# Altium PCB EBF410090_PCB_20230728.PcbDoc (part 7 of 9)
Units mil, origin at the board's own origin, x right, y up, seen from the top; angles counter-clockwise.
Board outline 5393.69 x 3858.26 mil, 6 copper layers (TOP, GND02, ART03, ART04, PWR05, BOTTOM), stack 47.2 mil thick; 570 components, 437 nets, 2015 pads, 1260 vias.
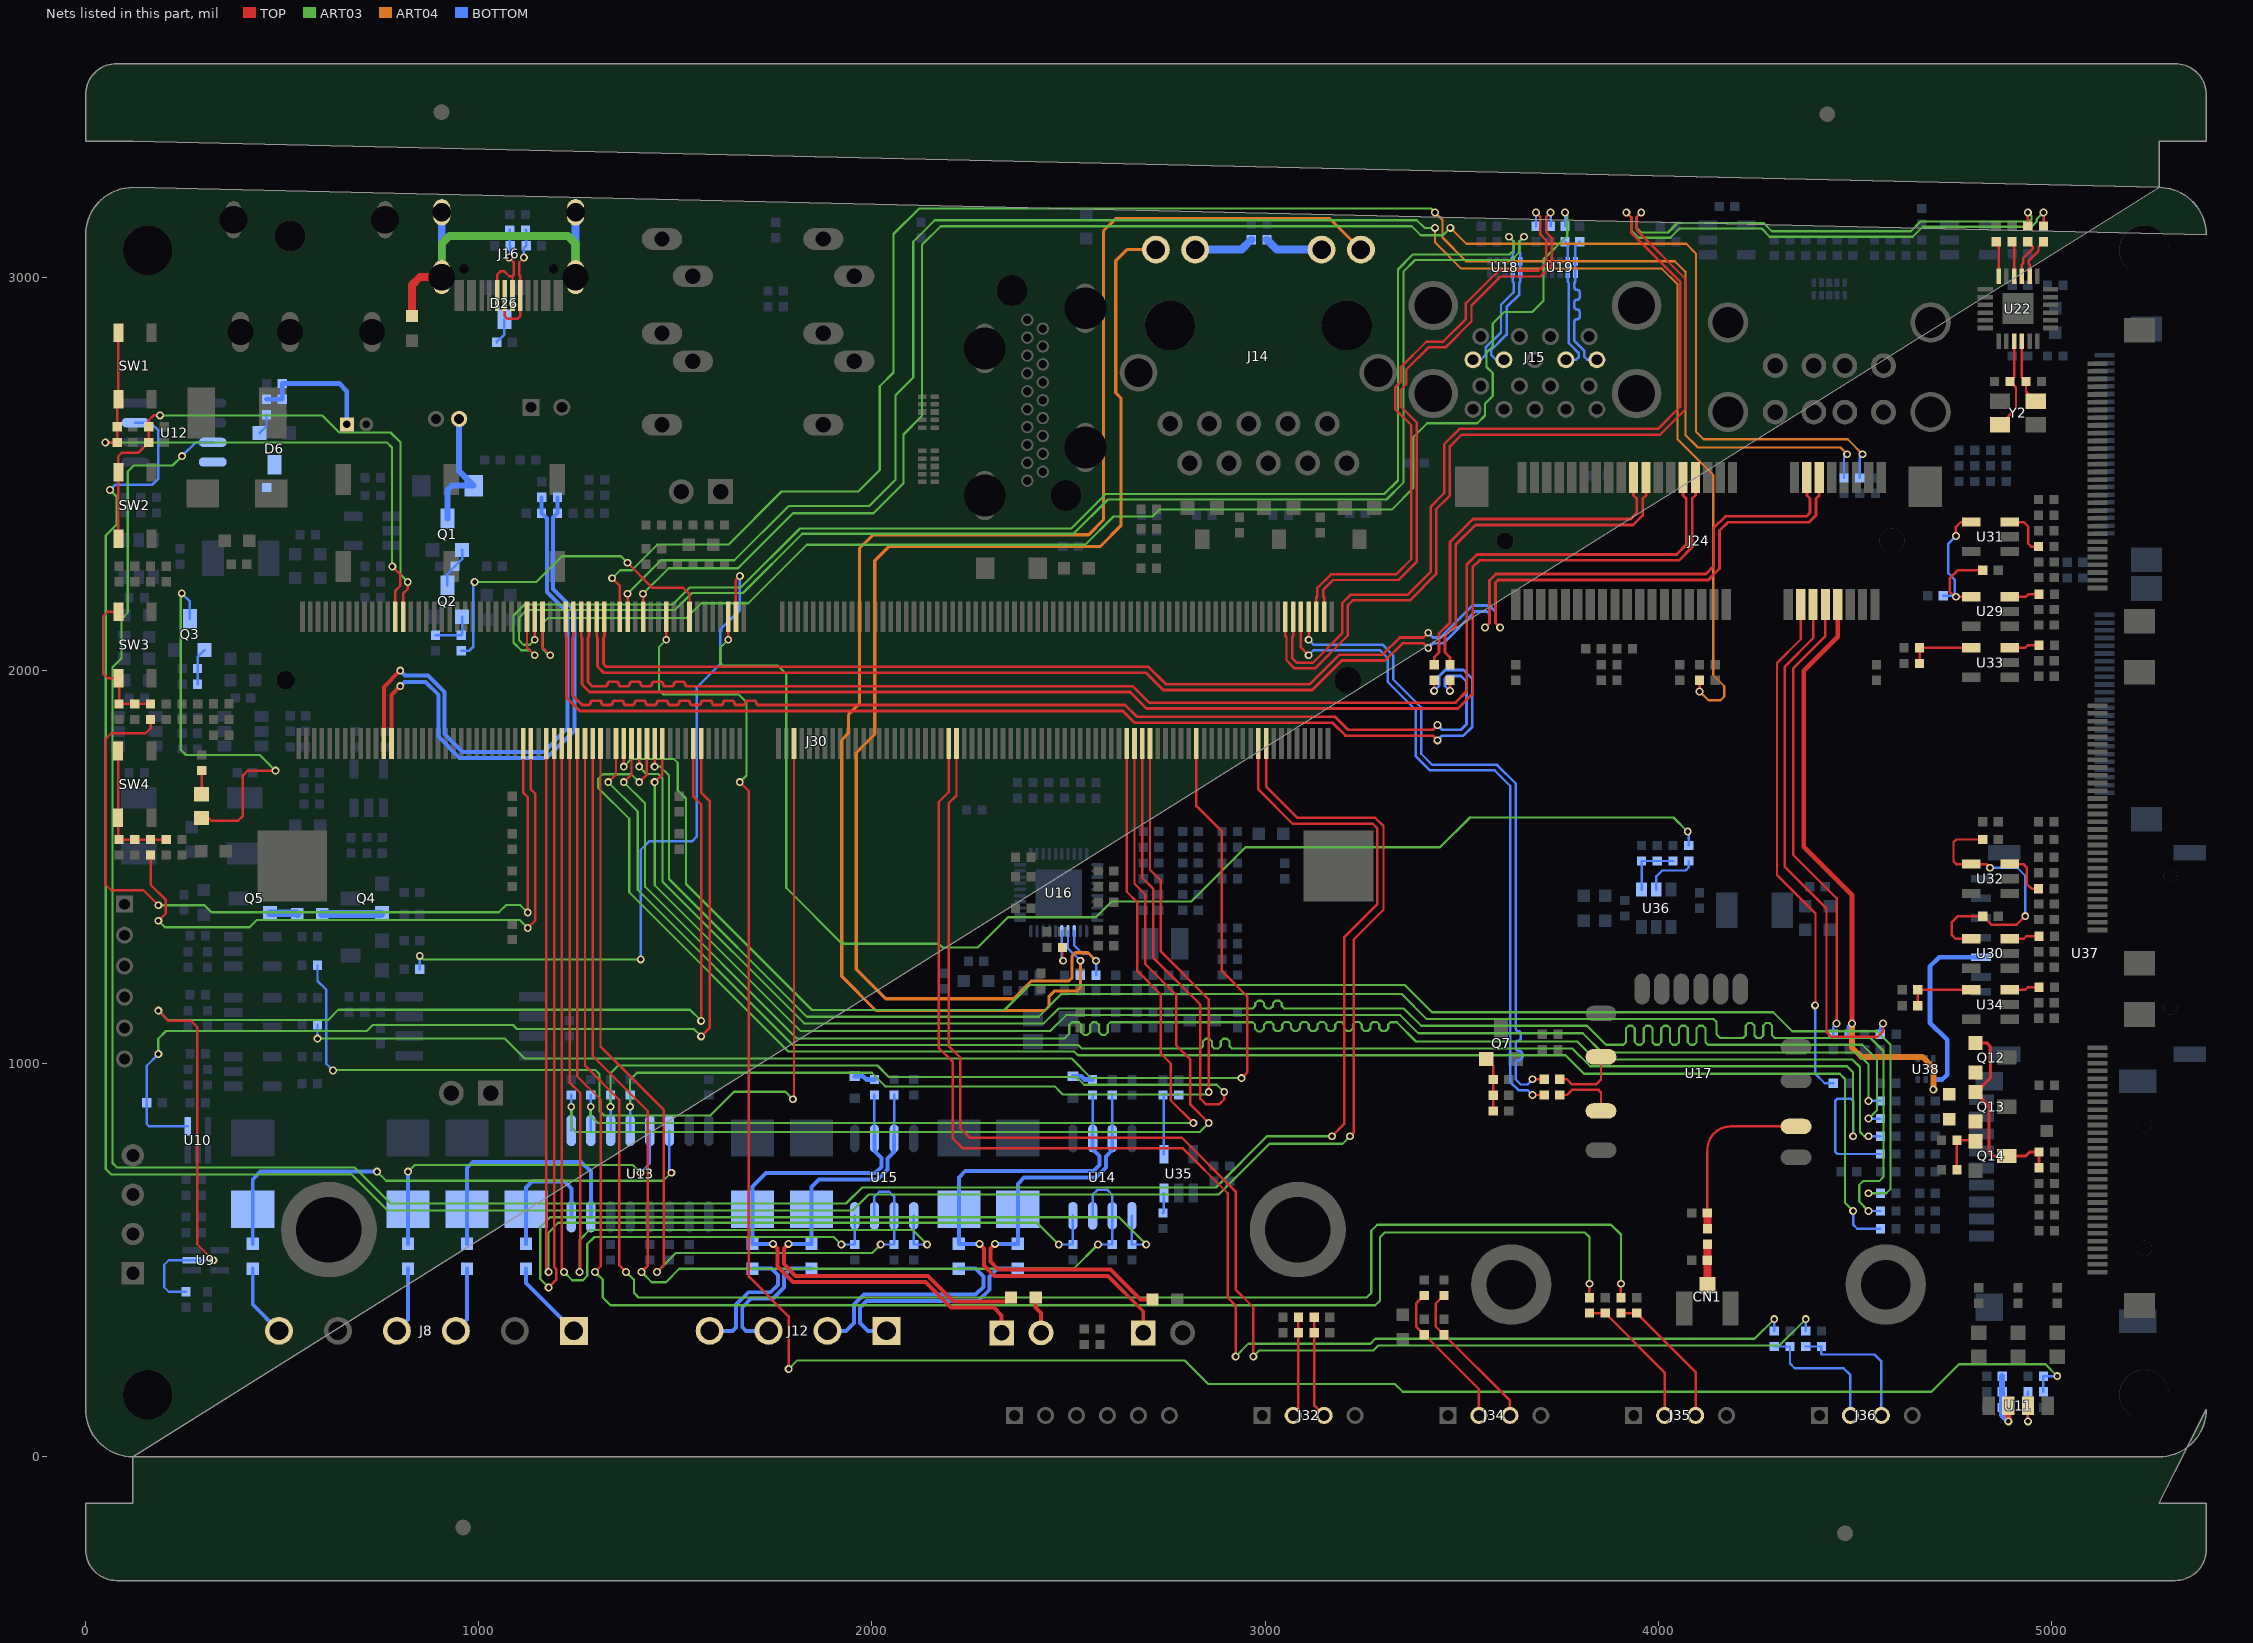
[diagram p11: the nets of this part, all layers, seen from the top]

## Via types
v1: diameter 20, hole 12, TOP to BOTTOM, 1260 vias

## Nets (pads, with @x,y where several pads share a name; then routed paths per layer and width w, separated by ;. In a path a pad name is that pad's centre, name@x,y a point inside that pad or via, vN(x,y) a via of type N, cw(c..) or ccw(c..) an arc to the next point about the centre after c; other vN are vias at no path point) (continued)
N17592172: C169.2 R203.2 R205.1 U36.4 | length 153.1
  BOTTOM w6.16: U36.4@3957.6,1442.24 R205.1@3957.6,1515.32 R203.2@3997.6,1515.32 C169.2@4037.6,1515.32
N17592286: R206.2 U36.5 | length 142.1
  BOTTOM w6.16: U36.5@3995,1442.24 3995,1476 4010,1491 4069.44,1491 4077.6,1499.16 R206.2@4077.6,1515.32
N17633217: C119.1 U22.3 Y2.1 | length 239.2
  TOP w6.16: Y2.1@4869.72,2625.47 4910,2665.75 4910,2719.68 C119.1@4894.68,2735 4905.16,2745.48 U22.3@4905.16,2837.32
N17633237: C120.2 U22.4 Y2.3 | length 167.5
  TOP w6.16: U22.4@4924.84,2837.32 4924.84,2745.48 C120.2@4935.32,2735 4935.32,2709.49 Y2.3@4960.28,2684.53
N17633305: R145.2 U22.16 | length 89.8
  TOP w6.16: R145.2@4900,3090.32 4905.16,3085.16 U22.16@4905.16,3002.68
N17633317: R146.2 U22.18 | length 90
  TOP w6.16: R146.2@4860,3090.32 4865.79,3084.53 U22.18@4865.79,3002.68
N17685591: C165.2 Q12.1 Q13.1 Q14.3 R196.2 | length 517.4
  TOP w8: Q12.1@4806.5,1052.5 4835.5,1052.5 4845,1043 4845,964 4808.5,927.5 Q13.1@4806.5,927.5 4841,893 4841,775 4851,765 Q14.3@4886.5,765 4935,765 4945,775 C165.2@4968.32,775 R196.2@4968.32,735
N17685601: Q14.1 R198.2 R199.1 | length 122.9
  TOP w6.16: R198.2@4759.68,730 R199.1@4759.68,805 4804,805 Q14.1@4806.5,802.5
N17685851: Q13.2 R194.2
N17690217: R195.1 U35.3 | length 52.2
  BOTTOM w6.16: R195.1@2740,619.68 2742.6,622.28 U35.3@2742.6,670.79
N17690290: C162.1 R193.2 U35.4 | length 192.2
  BOTTOM w6.16: U35.4@2742.6,769.21 2742.6,917.72 C162.1@2740,920.32 R193.2@2780,920.32
N17695706: C139.1 R172.2 U29.4 U31.4 | length 453.6
  TOP w6.16: v1(4757.19,2341.97) 4757.19,2365.08 4769.51,2377.4 U31.4@4795.79,2377.4 ; U29.4@4795.79,2187.4 v1(4757.19,2187.4) 4754.32,2187.4 4741,2200.72 4741,2233.68 4762.32,2255 C139.1@4825.32,2255
  BOTTOM w6.16: R172.2@4724.68,2190 v1@4754.59,2190 ; v1(4757.19,2187.4) v1@4754.59,2190 ; v1(4757.19,2341.97) 4738,2322.78 4738,2246.99 4754.59,2230.4 v1@4754.59,2190
N17695791: R175.1 U31.3 | length 124.6
  TOP w6.16: U31.3@4894.21,2377.4 4929.6,2377.4 4941,2366 4941,2322.16 4948.16,2315 R175.1@4967.32,2315
N17695827: R174.1 U29.3 | length 76.8
  TOP w6.16: U29.3@4894.21,2187.4 4935.4,2187.4 4942,2194 R174.1@4968.32,2194
N17697466: J14.13 R114.1 | length 153.2
  BOTTOM w20: J14.13@2822.1,3070.44 2940.12,3070.44 R114.1@2965,3095.32
N17697880: R182.1 U33.3 | length 76.8
  TOP w6.16: U33.3@4894.21,2057.4 4933.4,2057.4 4940,2064 R182.1@4968.32,2064
N17697953: C150.1 R180.2 U33.4 | length 171.1
  TOP w6.16: R180.2@4664.68,2017.4 C150.1@4664.68,2057.4 U33.4@4795.79,2057.4
N17701231: J11.2 R74.2 | length 95.6
  TOP w10: R74.2@2416.5,405 2416.5,379.25 2430,365.75 J11.2@2430,315
N17702194: J12.3 R81.2 | length 356
  BOTTOM w10: J12.3@1736.93,320.17 1679.83,320.17 1670,330 1670,380 1692.37,402.37 1748.63,402.37 1776.75,430.49 1776.75,461.24 1794.01,478.5 R81.2@1846.22,478.5
N17702199: J12.4 R82.2 | length 352.6
  BOTTOM w10: J12.4@1586.93,320.17 1645.17,320.17 1654,329 1654,386.63 1685.74,418.37 1742,418.37 1760.75,437.12 1760.75,462.5 1744.75,478.5 R82.2@1696.22,478.5
N17702222: J12.2 R80.2 | length 567.2
  BOTTOM w10: J12.2@1886.93,320.17 1934.17,320.17 1954,340 1954,386.63 1979.56,412.19 2263.5,412.19 2283.5,432.19 2283.5,458.5 2263.5,478.5 R80.2@2221.22,478.5
N17702231: J12.1 R79.2 | length 576.5
  BOTTOM w10: J12.1@2036.93,320.17 1989.83,320.17 1970,340 1970,380 1986.19,396.19 2270.13,396.19 2299.5,425.56 2299.5,458.5 2319.5,478.5 R79.2@2371.22,478.5
N17728858: D19.1 R71.1 | length 53.4
  BOTTOM w12: D19.1@2511.22,967.95 2532.06,967.95 2540.33,959.68 R71.1@2561.22,959.68
N17729021: D20.1 R72.1 | length 53.4
  BOTTOM w12: D20.1@1956.22,967.95 1977.06,967.95 1985.33,959.68 R72.1@2006.22,959.68
N17731599: J8.6 R59.2 | length 185.9
  BOTTOM w10: R59.2@425,478.5 425,386.83 J8.6@491.66,320.17
N17731608: J8.4 R58.2 | length 170.1
  BOTTOM w10: J8.4@791.66,320.17 820,348.51 R58.2@820,478.5
N17731627: J8.1 R56.2 | length 208.7
  BOTTOM w10: R56.2@1120,478.5 1120,441.83 J8.1@1241.66,320.17
N17748815: Q5.2 R26.2 | length 71
  BOTTOM w20: Q5.2@468.5,1382.5 536,1382.5 R26.2@538.5,1380
N17750545: Q1.1 Q2.3 R12.2 | length 105.5
  BOTTOM w6.16: Q2.3@920,2216.5 920,2245.32 R12.2@939.68,2265 957.5,2282.82 Q1.1@957.5,2306.5
N17750554: D2.1 J2.1 Q1.3 | length 328.6
  BOTTOM w15: Q1.3@920,2386.5 920,2457.99 932.01,2470 D2.1@986.93,2470 950.05,2506.88 J2.1@950.05,2639.93
N17750632: Q2.1 R17.2 R18.1 | length 112.9
  BOTTOM w6.16: R18.1@890,2089.68 R17.2@955,2089.68 957.5,2092.18 Q2.1@957.5,2136.5
N17759502: C67.1 D6.3 U12.8
N17770939: R142.1 U22.15 | length 104.6
  TOP w6.23: U22.15@4924.84,3002.68 4924.84,3032.16 4928.53,3035.85 4928.53,3048.65 4952.88,3073 4952.88,3077.44 R142.1@4940,3090.32
N17770942: R143.1 U22.14 | length 103.8
  TOP w6.23: U22.14@4944.53,3002.68 4944.53,3032.16 4942.76,3033.93 4942.76,3042.75 4967.11,3067.1 4967.11,3077.43 R143.1@4980,3090.32
N17861933: C65.1 C66.1 R47.1 U11.2 | length 160.8
  TOP w15: v1(4890.52,90) U11.2@4890.52,129.26
  BOTTOM w15: R47.1@4874.68,205 C66.1@4874.68,165 C65.1@4874.68,125 4874.68,105.84 v1(4890.52,90)
N17863087: R44.2 R46.2 U11.3 | length 114.3
  TOP w6.16: v1(4940.52,90) U11.3@4940.52,129.26
  BOTTOM w6.16: R46.2@4940.32,165 R44.2@4940.32,125 4940.32,90.2 v1(4940.52,90)
N17946485: C63.1 R43.1 SW3.3 SW3.4 Z5.2 | length 379.3
  TOP w6.16: SW3.4@82.99,2149.36 56.13,2149.36 44,2137.23 44,1992.19 56.13,1980.06 SW3.3@82.99,1980.06 85,1978.05 Z5.2@85,1914.68 C63.1@125,1914.68 R43.1@165,1914.68
N17975561: D7.2 J7.1 R50.2 R51.1 | length 337.8
  BOTTOM w12: R50.2@460,2689.68 R51.1@500,2689.68 499.68,2690 D7.2@499.68,2730 644.99,2730 664.37,2710.62 J7.1@664.37,2625.98
N18056005: C109.2 Q7.1 R127.2 R128.2 | length 139.4
  TOP w6.16: Q7.1@3562.5,1011.5 3580.32,993.68 C109.2@3580.32,959.44 R127.2@3580.32,919.44 R128.2@3580.32,879.44
N18056634: C106.1 C107.1 U17.2 | length 460.7
  TOP w6.16: C107.1@4125,619.68 C107.1@4124.68,620 4124.68,780.33 cw(c4184.42,780.33) 4184.42,840.07 U17.2@4350.45,840.07
  TOP w20: C106.1@4125,579.68 C107.1@4125,619.68
N18056637: C106.2 C108.1 CN1.1 | length 104.7
  TOP w6.16: C108.1@4125,499.68 C108.1@4124.68,500 C108.1@4125,500.32
  TOP w20: CN1.1@4125,435.86 C108.1@4125,499.68 ; C108.1@4125,500.32 C106.2@4125,540.32
N18057325: R126.2 U17.7 | length 172.9
  TOP w6.23: R126.2@3749.68,960 3767.78,960 3780.67,947.11 3841.92,947.11 3854.39,959.58 U17.7@3854.39,1017.23
N18057335: R125.2 U17.6 | length 159.8
  TOP w6.23: R125.2@3749.68,920 3767.79,920 3780.67,932.88 3848.16,932.88 3854.39,926.65 U17.6@3854.39,879.44
N18091011: D6.1 R50.1 | length 54.1
  BOTTOM w6.16: D6.1@442.5,2603.5 460,2621 R50.1@460,2650.32
N18111918: C136.1 R171.2 U30.4 U32.4 | length 722.7
  TOP w6.16: U30.4@4795.79,1317.4 4756.16,1317.4 4747,1326.56 4747,1360 4762,1375 C136.1@4825.32,1375 4847.32,1353 4911.37,1353 v1(4933.37,1375) ; R171.2@4825.32,1570 4758.16,1570 4751,1562.84 4751,1514.56 4758.16,1507.4 U32.4@4795.79,1507.4 4834.6,1507.4 v1(4844,1498)
  BOTTOM w6.16: v1(4844,1498) 4913,1498 4933.37,1477.63 v1(4933.37,1375)
N18111989: R176.1 U32.3 | length 123.4
  TOP w6.16: U32.3@4894.21,1507.4 4928.6,1507.4 4937,1499 4937,1457.32 4949.32,1445 R176.1@4967.32,1445
N18112037: R173.1 U30.3 | length 76.8
  TOP w6.16: U30.3@4894.21,1317.4 4929.4,1317.4 4936,1324 R173.1@4968.32,1324
N18115454: R188.1 U34.3 | length 76.8
  TOP w6.16: U34.3@4894.21,1187.4 4933.4,1187.4 4940,1194 R188.1@4968.32,1194
N18115527: C153.1 R187.2 U34.4 | length 176.1
  TOP w6.16: R187.2@4659.68,1147.4 C153.1@4659.68,1187.4 U34.4@4795.79,1187.4
N18173560: J16.C1 J16.C2 J16.C3 J16.C4 L8.1 | length 1020
  TOP w20: L8.1@830,2901.5 830,2980.28 850,3000.28 J16.C4@905.83,3000.28
  ART03 w20: J16.C4@905.83,3000.28 905.83,3085.75 925.08,3105 1226.78,3105 1246.03,3085.75 J16.C3@1246.03,3000.28
  BOTTOM w20: J16.C4@905.83,3000.28 J16.C2@905.83,3165.28 ; J16.C3@1246.03,3000.28 J16.C1@1246.03,3165.28
N18175084: D26.3 R138.1 | length 66.7
  BOTTOM w6.16: R138.1@1045.32,2835 1065,2854.68 D26.3@1065,2893.5
N18245213: LED4.1 Q3.3 | length 1038.3
  TOP w6.16: LED4.1@295,1624.68 312.37,1624.68 319.36,1617.69 387.68,1617.69 400,1630.01 400,1732.84 412.16,1745 v1(482.75,1745)
  ART03 w5.61: v1(244.37,2196) 242,2193.63 242,1798 255,1785 442.75,1785 v1(482.75,1745)
  BOTTOM w6.16: v1(244.37,2196) 265,2175.37 Q3.3@265,2131.5
N18245628: LED4.2 R16.2 | length 60
  TOP w6.16: LED4.2@295,1685.31 R16.2@295,1745.32
N18246356: Q3.1 R19.2 R21.1 | length 93.9
  BOTTOM w6.16: R19.2@284.68,1965 R21.1@284.68,2005 284.68,2033.68 Q3.1@302.5,2051.5
N18288623: C192.1 R232.1 R239.1 SW4.3 SW4.4 Z23.2 | length 346.3
  TOP w6.16: SW4.4@82.37,1794.94 SW4.3@82.37,1625.64 82.37,1572.31 Z23.2@85,1569.68 C192.1@125,1569.68 R232.1@165,1569.68 R239.1@205,1569.68
N18341998: J14.12 R111.1 | length 149.1
  BOTTOM w20: R111.1@3005,3095.32 3029.88,3070.44 J14.12@3143.76,3070.44
N18348384: J8.3 R57.2 | length 170.1
  BOTTOM w10: J8.3@941.66,320.17 970,348.51 R57.2@970,478.5
N18386455: Q12.2 R194.1
N18461230: Q4.2 R26.1 | length 153
  BOTTOM w6.16: Q4.2@751,1380 Q4.2@753.5,1382.5
  BOTTOM w20: R26.1@601.5,1380 Q4.2@751,1380
N18494968: D48.2 J34.2 R237.1 | length 380.1
  TOP w6.16: R237.1@3405,410.32 3384.12,389.44 3384.12,331.2 D48.2@3405,310.32 3543.82,171.5 J34.2@3543.82,105.01
N18494970: D47.2 J34.3 R238.1 | length 392
  TOP w6.16: R238.1@3455,410.32 3434.12,389.44 3434.12,331.2 D47.2@3455,310.32 3622.56,142.76 J34.3@3622.56,105.01
N18495009: D50.2 J32.2 R222.1 | length 255.5
  TOP w6.16: J32.2@3071.38,105.01 3084.68,118.31 D50.2@3084.68,315 R222.1@3084.68,355
N18495011: D49.2 J32.3 R233.1 | length 260.3
  TOP w6.16: R233.1@3125.32,355 D49.2@3125.32,315 3125.32,129.81 J32.3@3150.12,105.01
N18495097: D52.2 J35.2 R234.1 | length 363
  TOP w6.16: R234.1@3825,365.32 D52.2@3865,365.32 4016.26,214.06 J35.2@4016.26,105.01
N18495099: D51.2 J35.3 R225.1 | length 362.4
  TOP w6.16: R225.1@3905,365.32 D51.2@3945,365.32 4095,215.32 J35.3@4095,105.01
N18495175: D54.2 J36.2 R236.1 | length 351.6
  BOTTOM w6.16: R236.1@4295,280.32 D54.2@4335,280.32 4335,237.32 4347.32,225 4471.38,225 4488.7,207.68 J36.2@4488.7,105.01
N18495177: D53.2 J36.3 R235.1 | length 357.3
  BOTTOM w6.16: R235.1@4375,280.32 D53.2@4415,280.32 4415,260.32 4415.32,260 4550,260 4567.44,242.56 J36.3@4567.44,105.01
OTG0_DM: D33.2 J16.A7 J16.B7 R134.1 | length 325.6
  TOP w6.23: J16.A7@1066.13,2953.48 1066.13,2901.23 1073.36,2894 1098.2,2894 1105.43,2901.23 J16.B7@1105.43,2953.48 1105.43,3002.65 1102.7,3005.38 1102.7,3038.2 v1(1114.57,3050.07)
  BOTTOM w6.23: v1(1114.57,3050.07) 1114.57,3074.25 D33.2@1120.32,3080 1120.32,3119 R134.1@1119,3120.32
OTG0_DP: D34.2 J16.A6 J16.B6 R135.1 | length 275.4
  TOP w6.23: J16.B6@1046.43,2953.48 1046.43,3006.43 1055,3015 1065,3015 1077.36,3002.64 1085.73,3002.64 ; v1(1076.59,3050.07) 1088.47,3038.19 1088.47,3005.38 1085.73,3002.64 ; J16.A6@1085.73,2953.48 1085.73,3002.64
  BOTTOM w6.23: v1(1076.59,3050.07) 1079.68,3053.16 D34.2@1079.68,3080 1079,3080.68 R135.1@1079,3120.32
PCIE20_CLKREQN_M0: J30.177 R210.1 | length 4559.8
  TOP w6.16: v1(1339.05,2234.38) 1358.74,2214.69 J30.177@1358.74,2136.54
  ART03 w5.61: v1(1339.05,2234.38) 1359.61,2254.94 1388.95,2254.94 1454.01,2320 1635,2320 1770,2455 1965,2455 2020,2510 2020,2723 2055,2758 2055,3110 2120,3175 3421.89,3175 v1(3431.89,3165)
  ART04 w5.61: v1(3431.89,3165) 3451,3145.89 3451,3101 3511,3041 4042,3041 4069,3014 4069,2599 4101,2567 4463.37,2567 v1(4480.37,2550)
  BOTTOM w6.16: R210.1@4472.5,2489.68 4472.5,2542.13 v1(4480.37,2550)
PCIE20_PERSTN_M0: J30.175 R212.2 | length 4742.5
  TOP w6.16: J30.175@1378.42,2136.54 v1(1378.42,2195.01) ; v1(4105,1946.6) R212.2@4105,1975.32
  ART03 w5.61: v1(1378.42,2195.01) 1463.41,2280 1650,2280 1788,2418 1993,2418 2060,2485 2060,2700 2105,2745 2105,3090.4 2159.6,3145 3386,3145 3405.37,3125.63 v1(3431.89,3125.63)
  ART04 w5.61: v1(3431.89,3125.63) 3431.89,3089.11 3499,3022 4009,3022 4049,2982 4049,2588 4140,2497 4140,1988 4168,1960 4168,1933.61 4158.39,1924 4127.6,1924 v1(4105,1946.6)
PCIE20_REFCLKN: J24.11 J30.181 | length 3717.9
  TOP w7.03: J30.181@1319.37,2136.54 1319.37,2086.01 1317.04,2083.68 1317.04,2016.06 1324.07,2009.03 2703.23,2009.03 2747.23,1965.03 3113.77,1965.03 3188.74,2040 3298.74,2040 3342.74,2084 3403.1,2084 v1(3415,2095.9) ; v1(3597.9,2108.92) 3586,2120.82 3586,2222.97 3593.03,2230 4127.26,2230 4156,2258.74 4156,2355.88 4177.09,2376.97 4383.47,2376.97 4401.27,2394.77 4401.27,2436.81 4409.51,2445.05 J24.11@4409.51,2490.88
  BOTTOM w7.03: v1(3415,2095.9) 3426.9,2084 3446.77,2084 3527.8,2165.03 3570.18,2165.03 3586.01,2149.2 3586.01,2120.81 v1(3597.9,2108.92)
PCIE20_REFCLKP: J24.13 J30.183 | length 3717.8
  TOP w7.03: J30.183@1299.68,2136.54 1299.68,2086.01 1302.01,2083.68 1302.01,2009.83 1317.84,1994 2697,1994 2741,1950 3120,1950 3194.97,2024.97 3304.97,2024.97 3348.97,2068.97 3403.11,2068.97 v1(3415,2057.08) ; v1(3559.08,2108.92) 3570.97,2120.81 3570.97,2229.2 3586.8,2245.03 4121.03,2245.03 4140.97,2264.97 4140.97,2362.11 4170.86,2392 4377.24,2392 4386.24,2401 4386.24,2436.81 4378.01,2445.04 J24.13@4378.01,2490.88
  BOTTOM w7.03: v1(3415,2057.08) 3426.89,2068.97 3453,2068.97 3534.03,2150 3563.95,2150 3570.98,2142.97 3570.98,2120.82 v1(3559.08,2108.92)
PCIE20_RXN: J24.23 J30.187 | length 3562
  TOP w7.03: J30.187@1260.31,2136.54 1260.31,2086.01 1262.64,2083.68 1262.64,1964.1 1281.77,1944.97 2656.77,1944.97 2698.77,1902.97 3490.23,1902.97 3528,1940.74 3528,2262.74 3545.23,2279.97 4052.97,2279.97 4086.32,2313.32 4086.32,2436.81 4094.55,2445.04 J24.23@4094.55,2490.88
PCIE20_RXP: J24.25 J30.185 | length 3562.4
  TOP w7.03: J30.185@1280,2136.54 1280,2086.01 1277.67,2083.68 1277.67,1970.33 1288,1960 1322.13,1960 ccw(c1322.13,1965.5) 1327.63,1965.5 cw(c1333.13,1965.5) 1333.13,1971 1350.25,1971 cw(c1350.25,1965.5) 1355.75,1965.5 ccw(c1361.25,1965.5) 1361.25,1960 1378.37,1960 ccw(c1378.37,1965.5) 1383.87,1965.5 cw(c1389.37,1965.5) 1389.37,1971 1406.49,1971 cw(c1406.49,1965.5) 1411.99,1965.5 ccw(c1417.49,1965.5) 1417.49,1960 1434.61,1960 ccw(c1434.61,1965.5) 1440.11,1965.5 cw(c1445.61,1965.5) 1445.61,1971 1462.73,1971 cw(c1462.73,1965.5) 1468.23,1965.5 ccw(c1473.73,1965.5) 1473.73,1960 1490.85,1960 ccw(c1490.85,1965.5) 1496.35,1965.5 cw(c1501.85,1965.5) 1501.85,1971 1518.97,1971 cw(c1518.97,1965.5) 1524.47,1965.5 ccw(c1529.97,1965.5) 1529.97,1960 2663,1960 2705,1918 3484,1918 3512.97,1946.97 3512.97,2268.97 3539,2295 4046.74,2295 4071.29,2319.55 4071.29,2436.81 4063.05,2445.05 J24.25@4063.05,2490.88
PCIE20_TXN: C179.1 J30.189 | length 2862.5
  TOP w7.03: J30.189@1240.63,2136.54 1240.63,2086.01 1238.3,2083.68 1238.3,1936.7 1263,1912 1278.53,1912 ccw(c1278.53,1917.5) 1284.03,1917.5 cw(c1289.53,1917.5) 1289.53,1923 1306.65,1923 cw(c1306.65,1917.5) 1312.15,1917.5 ccw(c1317.65,1917.5) 1317.65,1912 1334.77,1912 ccw(c1334.77,1917.5) 1340.27,1917.5 cw(c1345.77,1917.5) 1345.77,1923 1362.89,1923 cw(c1362.89,1917.5) 1368.39,1917.5 ccw(c1373.89,1917.5) 1373.89,1912 1391.01,1912 ccw(c1391.01,1917.5) 1396.51,1917.5 cw(c1402.01,1917.5) 1402.01,1923 1419.13,1923 cw(c1419.13,1917.5) 1424.63,1917.5 ccw(c1430.13,1917.5) 1430.13,1912 1447.25,1912 ccw(c1447.25,1917.5) 1452.75,1917.5 cw(c1458.25,1917.5) 1458.25,1923 1475.37,1923 cw(c1475.37,1917.5) 1480.87,1917.5 ccw(c1486.37,1917.5) 1486.37,1912 1503.49,1912 ccw(c1503.49,1917.5) 1508.99,1917.5 cw(c1514.49,1917.5) 1514.49,1923 1531.61,1923 cw(c1531.61,1917.5) 1537.11,1917.5 ccw(c1542.61,1917.5) 1542.61,1912 1559.73,1912 ccw(c1559.73,1917.5) 1565.23,1917.5 cw(c1570.73,1917.5) 1570.73,1923 1587.85,1923 cw(c1587.85,1917.5) 1593.35,1917.5 ccw(c1598.85,1917.5) 1598.85,1912 1615.97,1912 ccw(c1615.97,1917.5) 1621.47,1917.5 cw(c1626.97,1917.5) 1626.97,1923 1644.09,1923 cw(c1644.09,1917.5) 1649.59,1917.5 ccw(c1655.09,1917.5) 1655.09,1912 1672.21,1912 ccw(c1672.21,1917.5) 1677.71,1917.5 cw(c1683.21,1917.5) 1683.21,1923 1700.33,1923 cw(c1700.33,1917.5) 1705.83,1917.5 ccw(c1711.33,1917.5) 1711.33,1912 2644,1912 2673.97,1882.03 3177.97,1882.03 3211,1849 3426.73,1849 v1(3438.63,1860.9) ; v1(3470,1948) C179.1@3470,1975.32
  BOTTOM w7.03: v1(3438.63,1860.9) 3450.53,1849 3497.94,1849 3511.97,1863.03 3511.97,1971.97 3497.94,1986 3464.54,1986 3457.51,1978.97 3457.51,1960.49 v1(3470,1948)
PCIE20_TXP: C180.1 J30.191 | length 2861.7
  TOP w7.03: J30.191@1220.94,2136.54 1220.94,2086.01 1223.27,2083.68 1223.27,1930.47 1256.77,1896.97 2637.77,1896.97 2667.74,1867 3171.74,1867 3204.77,1833.97 3426.74,1833.97 v1(3438.63,1822.08) ; v1(3430,1948) C180.1@3430,1975.32
  BOTTOM w7.03: v1(3430,1948) 3442.48,1960.48 3442.48,1985.2 3458.31,2001.03 3504.17,2001.03 3527,1978.2 3527,1856.8 3504.17,1833.97 3450.52,1833.97 v1(3438.63,1822.08)
PCIE20_WAKEN_M0: J30.171 R209.1 | length 4459.7
  TOP w6.16: J30.171@1417.79,2136.54 v1(1417.79,2195.01)
  ART03 w5.61: v1(1417.79,2195.01) 1482.78,2260 1658.99,2260 1798.99,2400 2003.99,2400 2080,2476.01 2080,2600.01 2127,2647.01 2127,3082.01 2174.99,3130 3373,3130 3396.18,3106.82 3452.45,3106.82 v1(3471.26,3125.63)
  ART04 w5.61: v1(3471.26,3125.63) 3511.89,3085 4071,3085 4096,3060 4096,2607 4115,2588 4481.74,2588 v1(4519.74,2550)
  BOTTOM w6.16: R209.1@4512.5,2489.68 4512.5,2542.76 v1(4519.74,2550)
PCIE_PWREN_EN: J30.149 R206.1 | length 3393.3
  TOP w6.16: v1(1634.33,2078.07) J30.149@1634.33,2136.54
  ART03 w5.61: v1(1634.33,2078.07) 1614,2057.74 1614,2020 1622,2012 1761,2012 1782,1991 1782,1447 1924,1305 2169.99,1305 2179.99,1295 2269,1295 2346,1372 2570,1372 2610,1412 2812,1412 2950,1550 3445,1550 3521,1626 4039,1626 v1(4075,1590)
  BOTTOM w6.16: v1(4075,1590) 4077.6,1587.4 R206.1@4077.6,1554.68
PE_TXN: C179.2 J24.31 | length 928.1
  TOP w7.03: C179.2@3470,2014.68 3470,2032.94 3457.51,2045.43 3457.51,2087.51 3485,2115 3485,2320 3534.97,2369.97 3936.23,2369.97 3960.33,2394.07 3960.33,2436.82 3968.56,2445.05 J24.31@3968.56,2490.88
PE_TXP: C180.2 J24.33 | length 928.1
  TOP w7.03: C180.2@3430,2014.68 3430,2032.95 3442.48,2045.43 3442.48,2093.74 3469.97,2121.23 3469.97,2326.23 3528.74,2385 3930,2385 3945.3,2400.3 3945.3,2436.82 3937.07,2445.05 J24.33@3937.07,2490.88
PHY1_LED1: J14.14 R116.1 U16.33 | length 3390
  ART04 w8: v1(2570,1261.48) 2549.48,1282 2517,1282 2509,1274 2509,1218 2501,1210 2405,1210 2360,1165 2035,1165 1960,1240 1960,1791 2007,1838 2007,2279 2043,2315 2580,2315 2633,2368 2633,2693 2620,2706 2620,3042 2648.44,3070.44 J14.14@2722.1,3070.44
  BOTTOM w6.16: U16.33@2514.37,1336.57 2514.37,1300.63 2535,1280 2551.48,1280 v1(2570,1261.48) R116.1@2570,1224.68
PHY1_LED2: J14.11 R117.1 U16.34 | length 4068.1
  ART04 w8: v1(2530,1261.48) 2530,1193 2522,1185 2465,1185 2450,1170 2450,1145 2440,1135 2010,1135 1923,1222 1923,1823 1940,1840 1940,1886.99 1968,1914.99 1968,2310 2003,2345 2551,2345 2589,2383 2589,3118 2620,3149 3165.2,3149 J14.11@3243.76,3070.44
  BOTTOM w6.16: U16.34@2498.62,1336.57 2498.62,1292.86 v1(2530,1261.48) R117.1@2530,1224.68
PHY_CLKOUT125: R113.2 U16.35 | length 110.6
  TOP w6.16: R113.2@2484.68,1295 2484.68,1263.01 v1(2486.21,1261.48)
  BOTTOM w6.16: U16.35@2482.87,1336.57 2482.87,1264.82 v1(2486.21,1261.48)
PWM2_M0: J30.159 R17.1 | length 872.6
  TOP w6.16: v1(1378.42,2273.75) 1442.17,2210 1520,2210 1535.91,2194.09 J30.159@1535.91,2136.54
  ART03 w5.61: v1(989.41,2225) 1146,2225 1211.56,2290.56 1361.61,2290.56 v1(1378.42,2273.75)
  BOTTOM w6.16: R17.1@955,2050.32 976.32,2050.32 985.33,2059.33 985.33,2220.92 v1(989.41,2225)
PWM3_IR: C64.1 J30.165 R46.1 | length 5569.8
  TOP w6.16: v1(1476.84,2078.07) J30.165@1476.85,2136.54 ; v1(1663.85,1715.86) 1687,1692.71 1687,458 1788.02,356.98 v1(1788.02,223.02)
  ART03 w5.61: v1(1476.84,2078.07) 1458.03,2059.26 1458.03,1950.97 1470,1939 1661,1939 1680.66,1919.34 1680.66,1732.67 v1(1663.85,1715.86) ; v1(1788.02,223.02) 1810,245 2795,245 2855,185 3329.99,185 3349.99,165 4695,165 4765,235 4985,235 v1(5015,205)
  BOTTOM w6.16: R46.1@4979.68,165 C64.1@4979.68,205 v1(5015,205)
PWR_3V3_EN: J30.36 R31.1 | length 3337.6
  TOP w6.16: J30.36@2825.28,1813.7 2825.28,1654.72 2890,1590 2890,1235 2955,1170 2955,978 v1(2940,963)
  ART03 w5.61: v1(589.68,1063.42) 1066.58,1063.42 1117,1013 2508,1013 2558,963 v1(2940,963)
  BOTTOM w6.16: v1(589.68,1063.42) R31.1@589.68,1098.42
PWR_5V_EN: J30.140 R33.1 | length 2495.4
  TOP w6.16: v1(1798.74,909.37) 1801.65,912.28 J30.140@1801.65,1813.7
  ART03 w5.61: v1(629.05,982.4) 630.65,984 1295.78,984 1307,972.78 1307,879.22 1318.22,868 1589,868 1649.18,928.18 1779.93,928.18 v1(1798.74,909.37)
  BOTTOM w6.16: R33.1@589.68,1250 589.68,1210.32 612,1188 612,999.45 v1(629.05,982.4)
PWR_12V_EN: J30.147 R29.1 | length 1850.9
  TOP w6.16: J30.147@1654.02,2136.54 1654.02,2229.97 v1(1664.05,2240)
  ART03 w5.61: v1(849.68,1274) 858.68,1265 v1(1412,1265)
  BOTTOM w6.16: R29.1@849.68,1240 v1(849.68,1274) ; v1(1412,1265) 1412,1544 1433,1565 1542,1565 1554,1577 1554,1956 1614.04,2016.04 1614.04,2104.04 1664.05,2154.05 v1(1664.05,2240)
PWRON_KEY: C60.1 J30.235 SW1.3 SW1.4 Z1.2 | length 1489.4
  TOP w6.16: v1(50,2580) C60.1@80.32,2580 Z1.2@80.32,2620 80.32,2687.39 SW1.3@82.99,2690.06 SW1.4@82.99,2859.36 ; v1(780,2264.37) 800,2244.37 800,2215 787.87,2202.87 J30.235@787.87,2136.54
  ART03 w5.61: v1(50,2580) 766,2580 779,2567 779,2265.37 v1(780,2264.37)
RECOVERY: J30.202 R43.2 | length 2070.5
  TOP w6.16: R43.2@165,1875.32 165,1853 152,1840 65,1840 51,1826 51,1455 65.08,1440.92 146.71,1440.92 v1(184.84,1402.79) ; J30.202@1112.67,1813.7 1112.67,1689.33 1124.37,1677.63 v1(1124.37,1384.15)
  ART03 w5.61: v1(184.84,1402.79) 302.21,1402.79 320,1385 1051,1385 1069,1403 1105.52,1403 v1(1124.37,1384.15)
RESET_KEY: C61.1 J30.233 SW2.3 SW2.4 Z4.2 | length 1488
  TOP w6.16: SW2.3@82.99,2335.06 SW2.4@82.99,2504.36 82.99,2544.83 92.16,2554 134.32,2554 Z4.2@160.32,2580 C61.1@160.32,2620 160.32,2636.36 172.65,2648.69 v1(188.91,2648.69) ; J30.233@807.56,2136.54 807.56,2195.56 819.37,2207.37 v1(819.37,2225)
  ART03 w5.61: v1(188.91,2648.69) 601.31,2648.69 645,2605 775.56,2605 800.56,2580 800.56,2243.81 v1(819.37,2225)
RS485_1_A: D23.2 J10.1 R71.2 R80.1 U14.6 | length 1345.8
  TOP w10: v1(2273.5,541.5) 2285,530 2285,485.96 2310.96,460 2600,460 2690,370 J10.1@2690,315
  BOTTOM w6.16: U14.6@2561.22,817.36 R71.2@2561.22,920.32
  BOTTOM w10: v1(2273.5,541.5) R80.1@2221.22,541.5 D23.2@2221.22,629.45 2221.22,710.37 2237.22,726.37 2563,726.37 2579,742.37 2579,765 2561.22,782.78 U14.6@2561.22,809.5 U14.6@2561.22,817.36
RS485_1_B: D21.2 R73.1 R76.1 R79.1 U14.7 | length 1145.9
  TOP w10: v1(2312.87,541.5) 2301,529.63 2301,496 2321,476 2606.63,476 2682.63,400 R73.1@2713.5,400
  BOTTOM w6.16: U14.7@2611.22,817.36 R76.1@2611.22,920.32
  BOTTOM w10: v1(2312.87,541.5) R79.1@2371.22,541.5 D21.2@2371.22,629.45 2371.22,694 2387.22,710 2566.43,710 2566.8,710.37 2569.63,710.37 2595,735.74 2595,764 2611.22,780.22 U14.7@2611.22,809.5 U14.7@2611.22,817.36
RS485_2_A: D24.2 J11.1 R72.2 R82.1 U15.6 | length 1465.5
  TOP w10: v1(1748.5,541.5) 1760,530 1760,483.37 1799.37,444 2136,444 2201,379 2310,379 2330,359 J11.1@2330,315
  BOTTOM w6.16: U15.6@2006.22,817.36 R72.2@2006.22,920.32
  BOTTOM w10: v1(1748.5,541.5) R82.1@1696.22,541.5 D24.2@1696.22,629.45 1696.22,687.59 1730,721.37 2008,721.37 2024,737.37 2024,760 2006.22,777.78 U15.6@2006.22,809.5 U15.6@2006.22,817.36
RS485_2_B: D22.2 R74.1 R78.1 R81.1 U15.7 | length 1289
  TOP w10: v1(1787.87,541.5) 1776,529.63 1776,490 1806,460 2142.63,460 2207.63,395 2343.5,395 R74.1@2353.5,405
  BOTTOM w6.16: U15.7@2056.22,817.36 R78.1@2056.22,920.32
  BOTTOM w10: v1(1787.87,541.5) R81.1@1846.22,541.5 D22.2@1846.22,629.45 1846.22,686.22 1865,705 2011.43,705 2011.8,705.37 2014.63,705.37 2040,730.74 2040,759 2056.22,775.22 U15.7@2056.22,809.5 U15.7@2056.22,817.36
RX8010_NIRQ1: J30.20 U12.7 | length 6528.1
  TOP w6.16: J30.20@2982.76,1813.7 2982.76,1697.24 3070,1610 3273.84,1610 3285,1598.84 3285,1405 3201,1321 3201,846 v1(3170,815)
  ART03 w5.61: v1(245,2545) 221,2521 122,2521 107,2506 107,2147 91,2131 91,2031 68.19,2008.19 68.19,747.22 79.41,736 684,736 776,644 1934,644 1975,685 2875,685 3005,815 v1(3170,815)
  BOTTOM w6.16: v1(245,2545) 280.07,2580.07 U12.7@323.28,2580.07
RX8010_NIRQ2: J30.18 U12.3 | length 6630.6
  TOP w6.16: J30.18@3002.44,1813.7 3002.44,1704.56 3082,1625 3280,1625 3301.16,1603.84 3301.16,1391.16 3225,1315 3225,824.08 v1(3215.92,815)
  ART03 w5.61: v1(61.68,2459.05) 78.49,2442.24 78.49,2370.49 51,2343 51,731.76 64.76,718 676.54,718 768.54,626 1951,626 1992,667 2882.01,667 3011.2,796.19 3197.11,796.19 v1(3215.92,815)
  BOTTOM w6.16: v1(61.68,2459.05) 74.63,2472 169,2472 185,2488 185,2610 164.93,2630.07 U12.3@126.42,2630.07
RXD1_232: D9.2 R58.1 U13.13 | length 907
  ART03 w5.61: v1(820,725) 836.81,741.81 1391.62,741.81 v1(1411.06,722.37)
  BOTTOM w6.16: v1(1411.06,722.37) 1435.2,746.51 U13.13@1435.2,829.8
  BOTTOM w10: R58.1@820,541.5 D9.2@820,629.45 v1(820,725)
RXD2_232: D8.2 R56.1 U13.8 | length 344.6
  BOTTOM w10: R56.1@1120,541.5 D8.2@1120,629.45 1120,685 1135,700 1217.88,700 1235.2,682.68 U13.8@1235.2,610.2
SARADC_VIN1: J30.200 R232.2 | length 1635.3
  TOP w6.16: R232.2@165,1530.32 165,1455 203.92,1416.08 203.92,1382.5 v1(184.84,1363.42) ; v1(1124.37,1344.78) 1144,1364.41 1144,1685.84 1132.35,1697.49 J30.200@1132.35,1813.7
  ART03 w5.61: v1(184.84,1363.42) 201.65,1346.61 416.61,1346.61 435,1365 1104.15,1365 v1(1124.37,1344.78)
SDMMC0_CLK: J30.178 R63.1 | length 4314
  TOP w6.16: v1(1329.2,1715.86) 1348.89,1735.55 J30.178@1348.89,1813.7
  ART03 w5.61: v1(1329.2,1715.86) 1404,1641.06 1404,1442 1798.83,1047.17 2524.83,1047.17 2534,1038 2835.55,1038 2842.12,1044.57 2842.12,1056.6 2848.69,1063.17 2857.99,1063.17 2864.56,1056.6 2864.56,1044.57 2871.13,1038 2880.43,1038 2887,1044.57 2887,1056.6 2893.57,1063.17 2902.87,1063.17 2909.44,1056.6 2909.44,1044.57 2916.01,1038 3782,1038 3826.83,993.17 4479.83,993.17 4495.63,977.37 v1(4495.63,815)
  BOTTOM w6.16: v1(4495.63,815) 4495.63,904.36 4488.99,911 4456.16,911 4450,904.84 4450,776.16 4456.16,770 R63.1@4565.32,770
SDMMC0_CMD: J30.176 R62.1 | length 4268.1
  TOP w6.16: v1(1368.57,1755.23) J30.176@1368.57,1813.7
  ART03 w5.61: v1(1368.57,1755.23) 1388.34,1775 1495.78,1775 1506,1764.78 1506,1694.99 1527,1673.99 1527,1456.99 1847.68,1136.31 2337.31,1136.31 2401,1200 3354.99,1200 3424.68,1130.31 4292.69,1130.31 4341,1082 4556,1082 4591,1047 4591,681.22 4579.78,670 v1(4535,670)
  BOTTOM w6.16: v1(4535,670) R62.1@4565.32,670
SDMMC0_D0: J30.174 R64.1 | length 4287.3
  TOP w6.16: v1(1368.57,1715.86) 1388.26,1735.55 J30.174@1388.26,1813.7
  ART03 w5.61: v1(1368.57,1715.86) 1423,1661.43 1423,1449.75 1808.75,1064 2490,1064 2502,1076 2502,1098 2509,1105 2525.95,1105 2532.52,1098.43 2532.52,1079.57 2539.09,1073 2548.39,1073 2554.96,1079.57 2554.96,1098.43 2561.53,1105 2570.83,1105 2577.4,1098.43 2577.4,1079.57 2583.97,1073 2593.27,1073 2599.84,1079.57 2599.84,1098.43 2606.41,1105 2968.07,1105 2974.64,1098.43 2974.64,1088.4 2981.21,1081.83 2990.51,1081.83 2997.08,1088.4 2997.08,1098.43 3003.65,1105 3015.62,1105 3021.23,1099.39 3021.23,1089.4 3027.8,1082.83 3037.1,1082.83 3043.67,1089.4 3043.67,1099.43 3050.24,1106 3059.54,1106 3066.11,1099.43 3066.11,1089.4 3072.68,1082.83 3081.98,1082.83 3088.55,1089.4 3088.55,1099.43 3095.12,1106 3104.42,1106 3110.99,1099.43 3110.99,1089.4 3117.56,1082.83 3126.86,1082.83 3133.43,1089.4 3133.43,1099.43 3140,1106 3149.3,1106 3155.87,1099.43 3155.87,1089.4 3162.44,1082.83 3171.74,1082.83 3178.31,1089.4 3178.31,1099.43 3184.88,1106 3194.18,1106 3200.75,1099.43 3200.75,1089.4 3207.32,1082.83 3216.62,1082.83 3223.19,1089.4 3223.19,1099.43 3229.76,1106 3239.06,1106 3245.63,1099.43 3245.63,1089.4 3252.2,1082.83 3261.5,1082.83 3268.07,1089.4 3268.07,1099.43 3274.64,1106 3283.94,1106 3290.51,1099.43 3290.51,1089.4 3297.08,1082.83 3306.38,1082.83 3312.95,1089.4 3312.95,1099.39 3318.56,1105 3335,1105 3384,1056 3794,1056 3840,1010 4494,1010 4513,991 4513,826 4524,815 v1(4535,815)
  BOTTOM w6.16: v1(4535,815) R64.1@4565.32,815
SDMMC0_D1: J30.172 R65.1 | length 4344.7
  TOP w6.16: v1(1407.94,1755.23) J30.172@1407.94,1813.7
  ART03 w5.61: v1(1407.94,1755.23) 1426.75,1736.42 1456.42,1736.42 1456.59,1736.59 1467.17,1726.02 1467.17,1462.4 1827.4,1102.17 2437.17,1102.17 2475,1140 2968.44,1140 2975.01,1146.57 2975.01,1153.41 2981.58,1159.98 2990.88,1159.98 2997.45,1153.41 2997.45,1146.57 3004.02,1140 3013.32,1140 3019.89,1146.57 3019.89,1153.41 3026.46,1159.98 3035.76,1159.98 3042.33,1153.41 3042.33,1146.57 3048.9,1140 3353,1140 3396.83,1096.17 3818.84,1096.17 3867.01,1048 3911.45,1048 3918.02,1054.57 3918.02,1089.6 3924.59,1096.17 3933.89,1096.17 3940.46,1089.6 3940.46,1054.57 3947.03,1048 3956.33,1048 3962.9,1054.57 3962.9,1089.6 3969.47,1096.17 3978.77,1096.17 3985.34,1089.6 3985.34,1054.57 3991.91,1048 4001.21,1048 4007.78,1054.57 4007.78,1089.6 4014.35,1096.17 4023.65,1096.17 4030.22,1089.6 4030.22,1054.57 4036.79,1048 4046.09,1048 4052.66,1054.57 4052.66,1089.6 4059.23,1096.17 4068.53,1096.17 4075.1,1089.6 4075.1,1054.57 4081.67,1048 4090.97,1048 4097.54,1054.57 4097.54,1089.6 4104.11,1096.17 4113.41,1096.17 4119.98,1089.6 4119.98,1054.57 4126.55,1048 4519,1048 4556.17,1010.83 4556.17,881.17 v1(4535,860)
  BOTTOM w6.16: v1(4535,860) R65.1@4565.32,860
SDMMC0_D2: J30.170 R60.1 | length 4286.9
  TOP w6.16: v1(1407.94,1715.86) 1427.63,1735.55 J30.170@1427.63,1813.7
  ART03 w5.61: v1(1407.94,1715.86) 1387.8,1736 1315.22,1736 1304,1724.78 1304,1701 1382.5,1622.5 1382.5,1435.5 1787.66,1030.34 2514.66,1030.34 2524,1021 3764,1021 3811,974 4461.99,974 4475,960.99 4475,645.63 v1(4495.63,625)
  BOTTOM w6.16: v1(4495.63,625) 4495.63,590.36 4505.99,580 R60.1@4565.32,580
SDMMC0_D3: J30.168 R61.1 | length 4322.7
  TOP w6.16: v1(1447.31,1755.23) J30.168@1447.31,1813.7
  ART03 w5.61: v1(1447.31,1755.23) 1461.77,1755.23 1484,1733 1484,1469.38 1834.38,1119 2424,1119 2481.81,1176.81 3347.19,1176.81 3411,1113 4141,1113 4148,1106 4148,1074.61 4157.61,1065 4215.73,1065 4222.3,1071.57 4222.3,1096.43 4228.87,1103 4238.17,1103 4244.74,1096.43 4244.74,1071.57 4251.31,1065 4260.61,1065 4267.18,1071.57 4267.18,1096.43 4273.75,1103 4283.05,1103 4289.62,1096.43 4289.62,1071.57 4296.19,1065 4540.01,1065 4573,1032.01 4573,712.22 4561.78,701 4520.61,701 4511,691.39 4511,649 v1(4535,625)
  BOTTOM w6.16: v1(4535,625) R61.1@4565.32,625
SDMMC0_DET_L: J30.166 R66.1 | length 3801
  TOP w6.16: v1(1447.31,1715.86) 1467,1735.55 J30.166@1467,1813.7
  ART03 w5.61: v1(1447.31,1715.86) 1447.31,1453.73 1817.87,1083.17 2454.17,1083.17 2494.17,1123.17 3343.82,1123.17 3389.82,1077.17 3807.84,1077.17 3857.01,1028 4505,1028 4535,998 v1(4535,905)
  BOTTOM w6.16: v1(4535,905) R66.1@4565.32,905
SIM_CLK0: J24.12 R202.1 | length 1366.2
  TOP w6.16: J24.12@4393.76,2168.04 4393.76,2081.76 4322,2010 4322,1500 4428,1394 4428,1080.32 4440.32,1068 4557.99,1068 4571.63,1081.64 v1(4571.63,1102.03)
  BOTTOM w6.16: R202.1@4565,1074.68 4565,1095.4 v1(4571.63,1102.03)
SIM_DATA0: J24.10 R204.1 | length 1176.7
  TOP w6.16: J24.10@4425.25,2168.04 4425.25,2087.25 4343,2005 4343,1531 4453.52,1420.48 v1(4453.52,1102.03)
  BOTTOM w6.16: R204.1@4445,1074.68 4445,1093.51 v1(4453.52,1102.03)
SIM_RST0: J24.14 R201.1 | length 1316.1
  TOP w6.16: J24.14@4362.26,2168.04 4362.26,2079.26 4302,2019 4302,1480 4400,1382 4400,1149 v1(4399,1148)
  BOTTOM w6.16: v1(4399,1148) 4399,974.32 4423.32,950 R201.1@4445.32,950
SIM_VDD: J24.8 R200.1 U37.1 U38.1 | length 2027.1
  TOP w12: J24.8@4456.75,2168.04 4456.75,2085.76 4370,1999.01 4370,1551 4492.89,1428.11 v1(4492.89,1102.03)
  ART04 w15: v1(4492.89,1102.03) 4492.89,1041 4516.89,1017 4672,1017 4699.64,989.36 v1(4699.64,934)
  BOTTOM w12: R200.1@4485,1074.68 4485,1094.14 v1(4492.89,1102.03) ; v1(4699.64,934) U38.1@4699.65,959.48 4722.64,959.48 4735,971.84 4735,1060 4691,1104 4691,1246.9 4714.26,1270.16 U37.1@4821.25,1270.16
SPKN_OUT: J30.236 R224.1 Z13.2 | length 1395.1
  TOP w10: J30.236@778.02,1813.7 778.02,1937.98 v1(800,1959.96)
  BOTTOM w6.16: R224.1@1200,2440.32 R224.1@1200.32,2440
  BOTTOM w10: v1(800,1959.96) 811.04,1971 864.04,1971 897,1938.04 897,1831.37 951.37,1777 1172.64,1777 1243,1847.36 1243,2152.63 1189,2206.63 1189,2388.68 Z13.2@1200.32,2400 R224.1@1200.32,2440
SPKP_OUT: J30.238 R223.1 Z11.2 | length 1416.6
  TOP w10: J30.238@758.34,1813.7 758.34,1957.67 v1(800,1999.33)
  BOTTOM w6.16: R223.1@1159.68,2440 R223.1@1160,2440.32
  BOTTOM w10: v1(800,1999.33) 812.33,1987 870.67,1987 913,1944.67 913,1838 958,1793 1166,1793 1226,1853 1226,2147 1173,2200 1173,2386.68 Z11.2@1159.68,2400 R223.1@1159.68,2440
SS_TXN: C114.1 J15.8 U19.2 U19.9 | length 343
  BOTTOM w6.23: C114.1@3763,3090.32 3769.69,3083.63 U19.9@3769.69,3040.75 U19.2@3769.69,3009.25 3769.69,2988.61 3772.41,2985.89 3772.41,2832.46 3797.27,2807.6 3797.27,2796.36 3791.03,2790.12 J15.8@3765.02,2790.12
SS_TXP: C115.1 J15.9 U19.1 U19.10 | length 373.9
  BOTTOM w6.23: C115.1@3800,3090.32 3789.37,3079.69 U19.10@3789.37,3040.75 U19.1@3789.37,3009.25 3789.37,2988.62 3786.64,2985.89 3786.64,2974.66 ccw(c3793.32,2974.66) 3793.32,2967.98 cw(c3793.32,2961.3) 3800,2961.3 3800,2949.74 cw(c3793.32,2949.74) 3793.32,2943.06 ccw(c3793.32,2936.38) 3786.64,2936.38 3786.64,2924.82 ccw(c3793.32,2924.82) 3793.32,2918.14 cw(c3793.32,2911.46) 3800,2911.46 3800,2899.9 cw(c3793.32,2899.9) 3793.32,2893.22 ccw(c3793.32,2886.54) 3786.64,2886.54 3786.64,2838.36 3811.5,2813.5 3811.5,2798.5 3819.88,2790.12 J15.9@3843.76,2790.12
TXD1_232: D11.2 R59.1 U13.14 | length 1364
  ART03 w5.61: v1(741.26,725) 764.26,702 1469.43,702 v1(1489.8,722.37)
  BOTTOM w6.16: U13.14@1484.8,829.8 1484.8,727.37 v1(1489.8,722.37)
  BOTTOM w10: R59.1@425,541.5 D11.2@425,629.45 425,705 445,725 v1(741.26,725)
TXD2_232: D10.2 R57.1 U13.7 | length 639.8
  BOTTOM w10: R57.1@970,541.5 D10.2@970,629.45 970,735 985,750 1260,750 1284.8,725.2 U13.7@1284.8,610.2
UART1_DIR: J30.184 R75.1 U14.2 U14.3 | length 2897.3
  TOP w6.16: J30.184@1289.83,1813.7 1289.83,1019.17 1430.14,878.86 1430.14,486.4 v1(1413.74,470)
  ART03 w5.61: v1(1413.74,470) 1439.74,444 1476,444 1510,478 2513.32,478 v1(2575,539.68)
  BOTTOM w6.16: U14.3@2561.22,612.64 2561.22,666.46 2573.54,678.78 2598.9,678.78 2611.22,666.46 U14.2@2611.22,612.64 R75.1@2611.22,539.68 v1(2575,539.68)
UART1_RX_M0: J30.194 R69.2 U14.1 | length 3245.1
  TOP w6.16: v1(1177.52,430.63) 1196.6,449.71 1196.6,477.91 1191.41,483.1 J30.194@1191.41,1813.7
  ART03 w5.61: v1(1177.52,430.63) 1156,452.15 1156,584 1181,609 2628.12,609 v1(2697.44,539.68)
  BOTTOM w6.16: U14.1@2661.22,612.64 R69.2@2661.22,539.68 v1(2697.44,539.68)
UART1_TX_M0: J30.196 R67.2 U14.4 | length 2886.3
  TOP w6.16: J30.196@1171.72,1813.7 1171.72,475.8 v1(1177.52,470)
  ART03 w5.61: v1(1177.52,470) 1177.52,570.52 1202,595 2419.68,595 v1(2475,539.68)
  BOTTOM w6.16: v1(2475,539.68) R67.2@2511.22,539.68 U14.4@2511.22,612.64
UART2_RX_M0_DEBUG: J30.156 R42.2 U10.4 | length 2505.2
  TOP w6.16: v1(1565.42,1069.19) 1587,1090.77 1587,1668 1565.42,1689.58 J30.156@1565.42,1813.7
  ART03 w5.61: v1(184.84,1024.05) 184.84,1063.42 204.42,1083 715,1083 730,1098 1087,1098 1097,1088 1546.61,1088 v1(1565.42,1069.19)
  BOTTOM w6.16: v1(184.84,1024.05) 155.32,994.53 R42.2@155.32,900 155.32,846.6 161.49,840.43 U10.4@259.72,840.43
UART2_TX_M0_DEBUG: J30.158 R39.2 U9.2 | length 3098.6
  TOP w6.16: v1(184.84,1134.68) 210.52,1109 267.55,1109 283.87,1092.68 283.87,540.49 v1(324.68,499.68) ; J30.158@1545.74,1813.7 1545.74,1679.26 1565.42,1659.58 v1(1565.42,1108.56)
  ART03 w5.61: v1(184.84,1134.68) 208.52,1111 617,1111 642.81,1136.81 1537.17,1136.81 v1(1565.42,1108.56)
  BOTTOM w6.16: R39.2@255,419.68 211.48,419.68 200,431.16 200,488.2 211.48,499.68 U9.2@269.57,499.68 v1(324.68,499.68)
UART3_RX_M1: J30.52 R52.2 U13.9 | length 2821.9
  TOP w6.16: J30.52@2667.79,1813.7 2667.79,1457.21 2695,1430 2695,1253.16 2774.08,1174.08 2774.08,1045.92 2810,1010 2810,895.54 v1(2856.77,848.77)
  ART03 w5.61: v1(1235.2,890) 1235.2,837.44 1246.43,826.21 2834.21,826.21 v1(2856.77,848.77)
  BOTTOM w6.16: R52.2@1235,920.32 1235.2,920.12 v1(1235.2,890) U13.9@1235.2,829.8
UART3_TX_M1: J30.54 R53.2 U13.10 | length 2689.3
  TOP w6.16: J30.54@2648.11,1813.7 2648.11,1436.89 2675,1410 2675,1235 2735,1175 2735,1025 2760,1000 2760,906.17 v1(2817.4,848.77)
  ART03 w5.61: v1(1284.8,890) 1284.8,866.2 1302.23,848.77 v1(2817.4,848.77)
  BOTTOM w6.16: U13.10@1284.8,829.8 v1(1284.8,890) 1285,890.2 R53.2@1285,920.32
UART4_RX_M1: J30.48 R54.2 U13.12 | length 2612.5
  TOP w6.16: J30.48@2707.16,1813.7 2707.16,1492.84 2735,1465 2735,1285 2856.77,1163.23 v1(2856.77,927.51)
  ART03 w5.61: v1(1384.8,890) 1384.8,958.8 1402.49,976.49 1999.51,976.49 2034,942 2465,942 2486,921 2850.26,921 v1(2856.77,927.51)
  BOTTOM w6.16: U13.12@1384.8,829.8 v1(1384.8,890) 1385,890.2 R54.2@1385,920.32
UART4_TX_M1: J30.50 R55.2 U13.11 | length 2827.1
  TOP w6.16: J30.50@2687.48,1813.7 2687.48,1472.52 2715,1445 2715,1270 2835,1150 2835,911 2849.15,896.85 2883.81,896.85 2896.14,909.18 v1(2896.14,927.51)
  ART03 w5.61: v1(1335.2,890) 1335.2,975.2 1355,995 2014,995 2043.45,965.55 2520.45,965.55 2539.68,946.32 2877.33,946.32 v1(2896.14,927.51)
  BOTTOM w6.16: R55.2@1335,920.32 1335,890.2 v1(1335.2,890) U13.11@1335.2,829.8
UART6_DIR: J30.182 R77.1 U15.2 U15.3 | length 2279.9
  TOP w6.16: J30.182@1309.52,1813.7 1309.52,1043.33 1470,882.85 1470,486.89 v1(1453.11,470)
  ART03 w5.61: v1(1453.11,470) 1501.11,518 2000.44,518 v1(2022.12,539.68)
  BOTTOM w6.16: U15.3@2006.22,612.64 2006.22,661.46 2018.54,673.78 2043.9,673.78 2056.22,661.46 U15.2@2056.22,612.64 R77.1@2056.22,539.68 v1(2022.12,539.68)
UART6_RX_M0: J30.190 R70.2 U15.1 | length 2454.2
  TOP w6.16: J30.190@1230.78,1813.7 1230.78,952.22 1258,925 1258,471.74 v1(1256.26,470)
  ART03 w5.61: v1(1256.26,470) 1256.26,551.26 1282,577 2103,577 v1(2140.32,539.68)
  BOTTOM w6.16: U15.1@2106.22,612.64 R70.2@2106.22,539.68 v1(2140.32,539.68)
UART6_TX_M0: J30.192 R68.2 U15.4 | length 2268
  TOP w6.16: J30.192@1211.09,1813.7 1211.09,475.8 v1(1216.89,470)
  ART03 w5.61: v1(1216.89,470) 1237.89,449 1264.78,449 1276,460.22 1276,540.99 1294.01,559 1902.8,559 v1(1922.12,539.68)
  BOTTOM w6.16: v1(1922.12,539.68) R68.2@1956.22,539.68 U15.4@1956.22,612.64
UART7_RX_M0: J30.186 R225.2 | length 4304.2
  TOP w6.16: J30.186@1270.15,1813.7 1270.15,994.85 1357,908 1357,487.37 v1(1374.37,470) ; R225.2@3905,404.68 v1(3905,440)
  ART03 w5.61: v1(1374.37,470) 1395,449.37 1395,416.22 1406.22,405 3258.78,405 3270,416.22 3270,575 3285,590 3880,590 3905,565 v1(3905,440)
UART7_TX_M0: J30.188 R234.2 | length 4295.5
  TOP w6.16: J30.188@1250.46,1813.7 1250.46,967.54 1310,908 1310,484.37 v1(1295.63,470) ; R234.2@3825,404.68 v1(3825,440)
  ART03 w5.61: v1(1295.63,470) 1315,450.63 1315,405 1335,385 3280,385 3292.5,397.5 3292.5,558.78 3303.72,570 3813.78,570 3825,558.78 v1(3825,440)
UART9_RX_M1: J30.98 R235.2 | length 3678.9
  TOP w6.16: J30.98@2215.04,1813.7 2215.04,1682.19 2195,1662.15 2195,1045.01 2224.69,1015.32 2224.69,835.31 2248.31,811.69 2788.12,811.69 2925,674.81 2925,425 2970,380 v1(2970,255)
  ART03 w5.61: v1(2970,255) 2985,270 3275,270 3287.62,282.62 4307.62,282.62 v1(4375,350)
  BOTTOM w6.16: R235.2@4375,319.68 v1(4375,350)
UART9_TX_M1: J30.100 R236.2 | length 3649.6
  TOP w6.16: J30.100@2195.35,1813.7 2195.35,1690.35 2170,1665 2170,1040 2205,1005 2205,810 2230,785 2790,785 2905,670 2905,405 2925,385 v1(2925,255)
  ART03 w5.61: v1(2925,255) 2957.38,287.38 3267.8,287.38 3280.42,300 4245,300 v1(4295,350)
  BOTTOM w6.16: R236.2@4295,319.68 v1(4295,350)
USB2_HOST2_DM: J30.7 R126.1 | length 1712.9
  TOP w6.23: v1(3110.69,2078.07) J30.7@3110.7,2136.54 ; v1(3680,960) R126.1@3710.32,960
  BOTTOM w6.23: v1(3110.69,2078.07) 3123.26,2065.5 3298.5,2065.5 3326,2038 3326,1977 3397,1906 3397,1788 3425.12,1759.88 3590.12,1759.88 3637.45,1712.55 3637.45,1089.07 ccw(c3643.72,1089.07) 3643.72,1082.8 ; 3643.72,1008.04 ccw(c3643.72,1001.77) 3637.45,1001.77 3637.45,959.47 3650.22,946.7 3667.23,946.7 3680,959.47 v1(3680,960) ; 3643.72,1032.96 cw(c3643.72,1039.23) 3637.45,1039.23 3637.45,1051.61 cw(c3643.72,1051.61) 3643.72,1057.88 ; 3643.73,1008.04 ccw(c3643.73,1019.31) 3655,1019.31 3655,1021.69 ccw(c3643.73,1021.69) 3643.73,1032.96 ; 3643.73,1057.88 ccw(c3643.73,1064.15) 3650,1064.15 3650,1076.53 ccw(c3643.73,1076.53) 3643.73,1082.8
USB2_HOST2_DP: J30.9 R125.1 | length 1725.4
  TOP w6.23: J30.9@3091.02,2136.54 3091.02,2058.37 v1(3110.69,2038.7) ; v1(3680,920) R125.1@3710.32,920
  BOTTOM w6.23: v1(3110.69,2038.7) 3123.26,2051.27 3292.6,2051.27 3311.77,2032.1 3311.77,1971.1 3382.77,1900.1 3382.77,1782.1 3419.22,1745.65 3584.22,1745.65 3623.22,1706.65 3623.22,953.57 3644.32,932.47 3667.53,932.47 v1(3680,920)
USB2_HOST3_DM: J30.11 R143.2 | length 3323.6
  TOP w6.23: J30.11@3071.33,2136.54 3071.33,2087.37 3068.6,2084.64 3068.6,2031.69 3081.06,2019.23 3121.04,2019.23 3195.77,2093.96 3195.77,2170.9 3217.1,2192.23 3362.22,2192.23 3420.77,2250.78 3420.77,2415.9 3455.77,2450.9 3455.77,2575.76 3494.24,2614.23 3999.22,2614.23 4055.77,2670.78 4055.77,2989.1 3930.77,3114.1 3930.77,3152.74 v1(3918.9,3164.61) ; R143.2@4980,3129.68 v1(4980,3165)
  ART03 w5.66: v1(3918.9,3164.61) 3931.06,3152.45 3931.06,3119.66 3950.38,3100.34 4030.66,3100.34 4054.66,3124.34 4262.34,3124.34 4283.34,3103.34 4647.66,3103.34 4672.66,3128.34 4949.33,3128.34 4962.99,3142 4962.99,3147.99 v1(4980,3165)
USB2_HOST3_DP: J30.13 R142.2 | length 3322.3
  TOP w6.23: J30.13@3051.65,2136.54 3051.65,2087.36 3054.37,2084.64 3054.37,2025.79 3075.16,2005 3126.94,2005 3210,2088.06 3210,2165 3223,2178 3368.12,2178 3435,2244.88 3435,2410 3470,2445 3470,2569.86 3500.14,2600 4005.12,2600 4070,2664.88 4070,2995 3945,3120 3945,3152.73 v1(3956.88,3164.61) ; R142.2@4940,3129.68 v1(4940,3165)
  ART03 w5.66: v1(3956.88,3164.61) 3944.72,3152.45 3944.72,3125.32 3956.04,3114 4025,3114 4049,3138 4268,3138 4289,3117 4642,3117 4667,3142 4943.67,3142 4949.33,3147.66 4949.33,3155.67 v1(4940,3165)
USB3_HOST1_DM: J30.3 R136.2 | length 1532.3
  TOP w6.23: J30.3@3150.07,2136.54 3150.07,2185.71 3147.34,2188.44 3147.34,2204.22 3173.12,2230 3339,2230 3386,2277 3386,2630 3345,2671 3345,2713.91 3359.03,2727.94 3359.03,2765.03 3415.77,2821.77 3458.78,2821.77 3525,2887.99 3525,2927.99 3599.01,3002 3700.13,3002 3729.23,3031.1 3729.23,3099.9 3714.62,3114.51 3714.62,3153.62 v1(3726,3165)
  BOTTOM w6.23: R136.2@3726,3129.68 v1(3726,3165)
USB3_HOST1_DP: J30.5 R137.2 | length 1532.3
  TOP w6.23: J30.5@3130.39,2136.54 3130.39,2185.72 3133.11,2188.44 3133.11,2210.12 3167.22,2244.23 3333.1,2244.23 3371.77,2282.9 3371.77,2624.1 3330.77,2665.1 3330.77,2719.81 3344.8,2733.84 3344.8,2770.93 3409.87,2836 3452.88,2836 3510.77,2893.89 3510.77,2933.89 3593.11,3016.23 3694.23,3016.23 3715,3037 3715,3094 3700.39,3108.61 3700.39,3153.61 v1(3689,3165)
  BOTTOM w6.23: R137.2@3689,3129.68 v1(3689,3165)
USB3_HOST1_SSRXN: J15.5 J30.201 U18.2 U18.9 | length 3899.3
  TOP w6.23: J30.201@1122.52,2136.54 1122.52,2058.38 v1(1142.2,2038.7)
  ART03 w5.66: v1(1142.2,2038.7) 1129.35,2051.55 1107.67,2051.55 1088.35,2070.87 1088.35,2139.67 1116.34,2167.66 1493.34,2167.66 1536.34,2210.66 1666.34,2210.66 1816.68,2361 2507,2361 2594.66,2448.66 3303.34,2448.66 3338,2483.32 3338,3020.03 3375.66,3057.69 3621.37,3057.69 3632.7,3069.02 3632.7,3090.87 v1(3620.54,3103.03)
  BOTTOM w6.23: J15.5@3528.8,2790.12 3548.59,2790.12 3561.05,2802.58 3561.05,2821.04 3600,2859.99 3600,2930 3632.42,2962.42 3632.42,2985.89 3629.69,2988.62 U18.2@3629.69,3009.25 U18.9@3629.69,3040.75 3629.69,3061.38 3632.41,3064.1 3632.41,3091.16 v1(3620.54,3103.03)
USB3_HOST1_SSRXP: J15.6 J30.199 U18.1 U18.10 | length 3829.2
  TOP w6.23: v1(1142.2,2078.07) J30.199@1142.2,2136.54
  ART03 w5.66: v1(1142.2,2078.07) 1129.34,2065.21 1113.33,2065.21 1102.01,2076.53 1102.01,2134.01 1122,2154 1499,2154 1542,2197 1672,2197 1822.34,2347.34 2512.66,2347.34 2600.32,2435 3309,2435 3351.66,2477.66 3351.66,3014.37 3381.32,3044.03 3627.03,3044.03 3646.36,3063.36 3646.36,3090.87 v1(3658.52,3103.03)
  BOTTOM w6.23: J15.6@3607.54,2790.12 3587.74,2790.12 3575.28,2802.58 3575.28,2815.14 3614.23,2854.09 3614.23,2924.1 3646.65,2956.52 3646.65,2985.89 3649.37,2988.61 U18.1@3649.37,3009.25 U18.10@3649.37,3040.75 3649.37,3061.37 3646.64,3064.1 3646.64,3091.15 v1(3658.52,3103.03)
USB3_HOST1_SSTXN: C114.2 J30.197 | length 3583.7
  TOP w6.23: J30.197@1161.89,2136.54 1161.89,2058.38 v1(1181.57,2038.7)
  ART03 w5.66: v1(1181.57,2038.7) 1178.4,2038.7 1162.74,2054.36 1162.74,2120 1176.4,2133.66 1528.33,2133.66 1565.67,2171 1685.67,2171 1834.33,2319.66 2542.34,2319.66 2614.34,2391.66 2713.35,2391.66 2730.69,2409 3322,2409 3377,2464 3377,2593.32 3412.34,2628.66 3539.34,2628.66 3559.34,2648.66 3559.34,2678.37 3578.98,2698.01 3578.98,2756.24 3563.39,2771.83 3563.39,2808.41 3578.98,2824 3578.98,2882.31 3608.67,2912 3680,2912 3708,2940 3708,3045 3768.67,3105.67 3768.67,3159.33 v1(3763,3165)
  BOTTOM w6.23: C114.2@3763,3129.68 v1(3763,3165)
